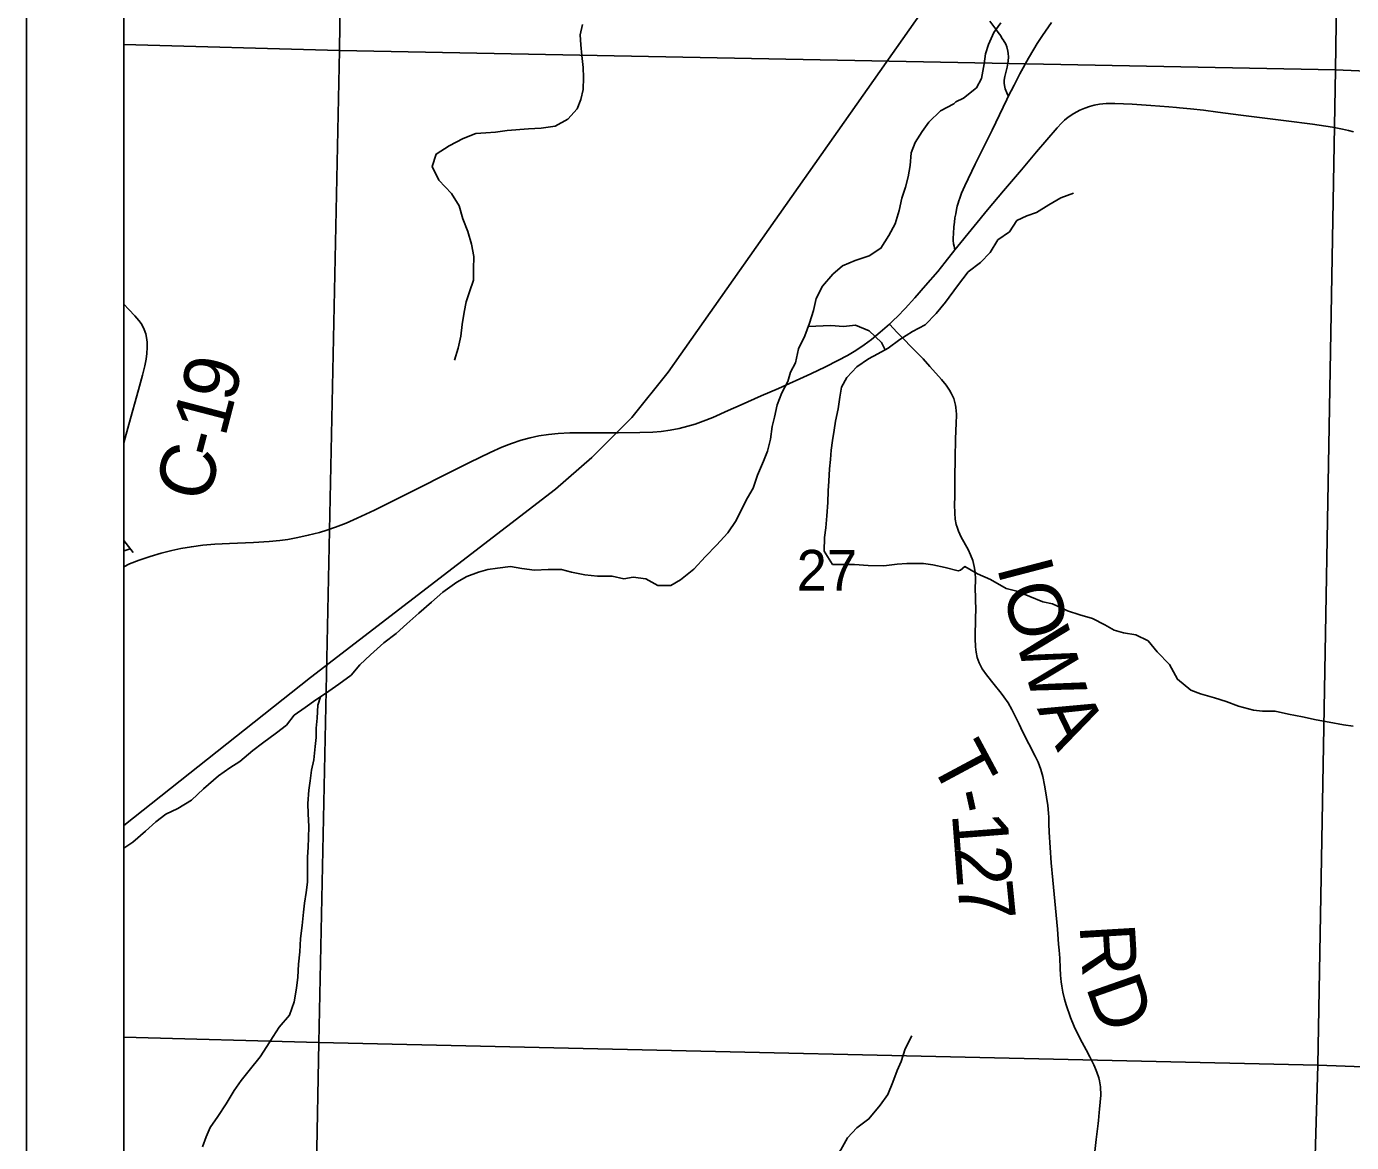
# Model space of a CAD drawing. Extents: x 0 to 34, y 0 to 22.
# Drawn here: x 2 to 3.363, y 16.577 to 17.725 of the extents above; entities that cross this region are included whole.
import ezdxf

# ---------------------------------------------------------------- set-up
doc = ezdxf.new("R2010")
doc.units = 0
for name, color, linetype in [('GM_X_Corporation', 7, 'Continuous'), ('GM_X_County_Road', 7, 'Continuous'), ('GM_X_County_Road_Text', 7, 'Continuous'), ('GM_X_Minor_River', 7, 'Continuous'), ('GM_X_Rail_Line', 7, 'Continuous'), ('GM_X_Section_Text', 7, 'Continuous'), ('GM_X_State_Route', 7, 'Continuous'), ('GM_X_Township_Road', 7, 'Continuous'), ('GM_X_Township_Road_Text', 7, 'Continuous'), ('SH_Data', 7, 'Continuous')]:
    doc.layers.add(name, color=color, linetype=linetype)

msp = doc.modelspace()

# ---------------------------------------------------------------- linework, layer by layer
at = {"layer": 'GM_X_Corporation'}
for points in [[(8.9, 20.9), (2.1, 20.9), (2.1, 15.6606)], [(5.3543, 16.3597), (5.3699, 17.5116), (5.3717, 17.6123), (4.6401, 17.6298), (4.3705, 17.6391), (4.3669, 17.8198), (4.37, 17.9048), (4.3768, 18.4091), (4.3782, 18.6502), (4.377, 18.6713), (3.7035, 18.69), (3.3642, 18.7005), (3.3691, 19.5041), (3.3724, 19.7263), (3.3869, 20.7918), (3.3886, 20.9), (2.1, 20.9), (2.1, 15.6606)], [(4.352, 16.8239), (4.3481, 16.6188), (3.3284, 16.656), (3.3465, 17.6805), (4.3675, 17.6365), (4.3565, 17.0622)]]:
    msp.add_lwpolyline(points, dxfattribs=at)
for points in [[(2.1, 18.7299), (2.1, 17.7065), (2.3219, 17.7003), (2.3352, 18.7231)], [(2.3352, 18.7231), (3.3614, 18.7006), (3.3465, 17.6805), (2.3219, 17.7003)], [(4.3772, 18.6714), (4.3675, 17.6365), (3.3465, 17.6805), (3.3614, 18.7006)], [(2.1, 17.7065), (2.1, 16.6849), (2.3008, 16.6793), (2.3219, 17.7003)], [(2.3219, 17.7003), (3.3465, 17.6805), (3.3284, 16.656), (2.3008, 16.6793)], [(2.1, 16.6849), (2.1, 15.6631), (2.2815, 15.6586), (2.3008, 16.6793)], [(2.3008, 16.6793), (3.3284, 16.656), (3.2981, 15.6275), (2.3289, 15.6573), (2.2815, 15.6586)]]:
    msp.add_lwpolyline(points, close=True, dxfattribs=at)
at = {"layer": 'GM_X_County_Road'}
msp.add_lwpolyline([(2.1, 17.2956), (2.1006, 17.2979), (2.1054, 17.3153), (2.1151, 17.3511), (2.1192, 17.366), (2.1216, 17.3756), (2.1231, 17.3828), (2.1238, 17.3883), (2.1242, 17.3945), (2.124, 17.4001), (2.1234, 17.405), (2.1226, 17.4086), (2.1209, 17.4133), (2.1196, 17.4161), (2.1178, 17.4194), (2.1156, 17.4224), (2.1116, 17.4271), (2.1052, 17.4339), (2.1, 17.4391)], dxfattribs=at)
at = {"layer": 'GM_X_Minor_River'}
for points in [[(2.5718, 17.7271), (2.5696, 17.7164), (2.5701, 17.7062), (2.5714, 17.6952), (2.5726, 17.6827), (2.5731, 17.6725), (2.5725, 17.66), (2.5703, 17.6497), (2.5663, 17.6402), (2.5569, 17.6295), (2.5437, 17.6225), (2.5294, 17.6205), (2.5165, 17.6196), (2.4946, 17.6178), (2.4825, 17.6162), (2.4726, 17.6157), (2.4621, 17.6148), (2.4492, 17.6098), (2.4349, 17.6021), (2.4214, 17.5936), (2.4174, 17.581), (2.4243, 17.5667), (2.4373, 17.5532), (2.445, 17.5404), (2.449, 17.5271), (2.454, 17.5139), (2.4576, 17.5011), (2.46, 17.4882), (2.4597, 17.4753), (2.4598, 17.464), (2.4558, 17.4518), (2.4521, 17.4415), (2.4503, 17.4309), (2.4482, 17.4183), (2.4468, 17.4062), (2.4439, 17.394), (2.4402, 17.3815)], [(2.956, 17.6473), (2.964, 17.6511), (2.9772, 17.6619), (2.9825, 17.6714), (2.985, 17.6866), (2.9864, 17.6968), (2.9894, 17.7063), (2.995, 17.7189), (3.0021, 17.7288)], [(2.956, 17.6473), (2.9538, 17.6454), (2.9402, 17.6381), (2.9282, 17.6266), (2.9215, 17.617), (2.9141, 17.6056), (2.91, 17.5949), (2.909, 17.582), (2.9069, 17.5702), (2.9043, 17.5596), (2.9003, 17.5482), (2.8978, 17.5356), (2.8934, 17.5219), (2.887, 17.5098), (2.8789, 17.4968), (2.8668, 17.4891), (2.8525, 17.484), (2.8393, 17.4785), (2.8295, 17.4701), (2.8187, 17.4579), (2.8124, 17.4449), (2.8095, 17.4327), (2.8055, 17.4198), (2.8007, 17.4065), (2.794, 17.3932), (2.7911, 17.3787), (2.7859, 17.3692), (2.783, 17.3597), (2.7771, 17.3479), (2.7723, 17.3357), (2.7694, 17.3228), (2.7672, 17.3133), (2.7654, 17.3004), (2.7622, 17.2878), (2.7581, 17.2775), (2.7518, 17.2631), (2.7474, 17.2498), (2.7418, 17.2399), (2.7348, 17.2265), (2.73, 17.2166), (2.7214, 17.204), (2.7098, 17.1914), (2.6986, 17.1795), (2.6866, 17.1665), (2.6727, 17.1557), (2.6629, 17.1496), (2.6493, 17.1498), (2.6371, 17.1565), (2.6242, 17.1583), (2.6144, 17.1566), (2.6023, 17.1592), (2.5875, 17.1594), (2.5742, 17.1608), (2.5606, 17.1633), (2.5503, 17.1662), (2.5367, 17.1661), (2.5227, 17.1655), (2.5094, 17.1673), (2.4977, 17.1694), (2.4845, 17.1674), (2.4746, 17.1662), (2.4648, 17.1634), (2.4528, 17.1591), (2.4426, 17.1533), (2.4283, 17.1429), (2.4167, 17.1326), (2.4036, 17.1214), (2.3912, 17.1103), (2.3803, 17.1004), (2.3675, 17.0907), (2.3537, 17.0785), (2.3428, 17.0681), (2.3338, 17.0574), (2.3214, 17.0482), (2.3075, 17.0386), (2.2977, 17.032), (2.2865, 17.0243), (2.2752, 17.0162), (2.2674, 17.0059), (2.2572, 16.9982), (2.2426, 16.9875), (2.2328, 16.9798), (2.2193, 16.9686), (2.2091, 16.9621), (2.1975, 16.954), (2.1821, 16.9406), (2.1697, 16.9287), (2.1555, 16.9202), (2.1434, 16.9144), (2.1329, 16.9067), (2.1224, 16.8971), (2.1093, 16.8856), (2.1, 16.8796)], [(2.9578, 17.4582), (2.9687, 17.4724), (2.9812, 17.482), (2.9913, 17.4923), (2.9992, 17.5053), (3.0113, 17.5138), (3.0188, 17.5252), (3.029, 17.5302), (3.0388, 17.5337), (3.0516, 17.5414), (3.0641, 17.5487), (3.0769, 17.5534)], [(2.9606, 17.1656), (2.9584, 17.1648), (2.9451, 17.1681), (2.9322, 17.171), (2.9227, 17.1724), (2.9057, 17.1722), (2.8955, 17.1717), (2.8818, 17.1701), (2.8659, 17.1703), (2.8519, 17.1713), (2.8421, 17.1712), (2.8292, 17.1714), (2.8204, 17.185), (2.821, 17.199), (2.8224, 17.2092), (2.8234, 17.2214), (2.8244, 17.235), (2.8247, 17.2472), (2.8253, 17.257), (2.8259, 17.2699), (2.827, 17.2794), (2.8276, 17.2889), (2.829, 17.2988), (2.8308, 17.3094), (2.8322, 17.3189), (2.8348, 17.3314), (2.8365, 17.3436), (2.8383, 17.3538), (2.8439, 17.3637), (2.854, 17.3748), (2.866, 17.3829), (2.8758, 17.388), (2.8863, 17.3941), (2.8984, 17.403), (2.9115, 17.4111), (2.9243, 17.418), (2.9359, 17.4295), (2.9453, 17.4414), (2.9578, 17.4582)], [(2.8834, 17.3924), (2.8795, 17.3997), (2.8669, 17.4117), (2.8528, 17.4177), (2.8403, 17.4164), (2.8274, 17.4174), (2.804, 17.4164)], [(2.1, 17.196), (2.1, 17.196), (2.1096, 17.1836)], [(2.1065, 17.1876), (2.1005, 17.1854), (2.1, 17.1854)], [(2.9606, 17.1656), (2.9652, 17.1692), (2.9781, 17.1617), (2.9915, 17.1558), (3.0078, 17.1468), (3.0188, 17.1438), (3.0321, 17.1383), (3.0454, 17.133), (3.0553, 17.1308), (3.0709, 17.1238), (3.0835, 17.1197), (3.0964, 17.1156), (3.1093, 17.1093), (3.1188, 17.1037), (3.1283, 17.1011), (3.1412, 17.0989), (3.1538, 17.0929), (3.163, 17.0816), (3.1756, 17.0684), (3.184, 17.0533), (3.1977, 17.0421), (3.2076, 17.0383), (3.2221, 17.0343), (3.2342, 17.0302), (3.2468, 17.0254), (3.262, 17.0213), (3.2714, 17.0203), (3.2843, 17.0204), (3.298, 17.0174), (3.3124, 17.0145), (3.3265, 17.0116), (3.3401, 17.009), (3.3549, 17.0065), (3.3648, 17.0051)], [(2.3024, 17.0352), (2.2997, 17.0267), (2.2991, 17.0131), (2.298, 17.0028), (2.2978, 16.9933), (2.2971, 16.9839), (2.2954, 16.9702), (2.2932, 16.9596), (2.2918, 16.9486), (2.2904, 16.9391), (2.2894, 16.9254), (2.2899, 16.9148), (2.2904, 16.9019), (2.2901, 16.8902), (2.2899, 16.8803), (2.2892, 16.8701), (2.2889, 16.8606), (2.2891, 16.8443), (2.2877, 16.8337), (2.2859, 16.823), (2.2849, 16.8135), (2.2835, 16.7999), (2.2817, 16.7866), (2.2811, 16.7729), (2.2797, 16.76), (2.2791, 16.7468), (2.2777, 16.7354), (2.2752, 16.7213), (2.2704, 16.7076), (2.26, 16.6954), (2.2536, 16.6858), (2.2473, 16.6755), (2.2402, 16.6648), (2.229, 16.6507), (2.2208, 16.6404), (2.2137, 16.6301), (2.2055, 16.6163), (2.1969, 16.6034), (2.1891, 16.5919), (2.1847, 16.5824), (2.181, 16.5721)], [(2.7713, 16.5074), (2.7853, 16.5148), (2.7973, 16.5221), (2.8082, 16.5298), (2.8202, 16.5401), (2.825, 16.5497), (2.8295, 16.5592), (2.8377, 16.5691), (2.8444, 16.5813), (2.8541, 16.5917), (2.8665, 16.6009), (2.8781, 16.6151), (2.8859, 16.6258), (2.8911, 16.6387), (2.8955, 16.6505), (2.8996, 16.66), (2.904, 16.6729), (2.9107, 16.6863)]]:
    msp.add_lwpolyline(points, dxfattribs=at)
at = {"layer": 'GM_X_Rail_Line'}
msp.add_lwpolyline([(3.6829, 18.8279), (3.1625, 18.0833), (2.66, 17.3693), (2.6227, 17.3226), (2.5817, 17.2815), (2.544, 17.2487), (2.292, 17.055), (2.1, 16.9029)], dxfattribs=at)
at = {"layer": 'GM_X_State_Route'}
msp.add_line((2.8876, 17.4186), (2.8918, 17.4227), dxfattribs=at)
for points in [[(3.0099, 17.6528), (3.0159, 17.6646), (3.0219, 17.6762), (3.0308, 17.6925), (3.0361, 17.7016), (3.0397, 17.7074), (3.0452, 17.7156), (3.0543, 17.7289)], [(2.955, 17.495), (2.9541, 17.499), (2.9537, 17.5013), (2.9533, 17.5046), (2.9533, 17.5071), (2.9535, 17.5121), (2.9539, 17.5188), (2.9545, 17.5237), (2.9551, 17.528), (2.9558, 17.5323), (2.9566, 17.5365), (2.9574, 17.5399), (2.9583, 17.5431), (2.9591, 17.5457), (2.96, 17.5483), (2.9619, 17.5535), (2.9651, 17.5609), (2.976, 17.5832), (2.9878, 17.6072), (2.9932, 17.6184), (3.0084, 17.6497), (3.0099, 17.6528)], [(2.955, 17.495), (2.9747, 17.5196), (2.9886, 17.5362), (3.0049, 17.5557), (3.0234, 17.5775), (3.0389, 17.5959), (3.0603, 17.6208), (3.0646, 17.6254), (3.0678, 17.6284), (3.0716, 17.6317), (3.0774, 17.6354), (3.0835, 17.6387), (3.0886, 17.641), (3.0934, 17.6427), (3.0982, 17.644), (3.1038, 17.645), (3.1106, 17.6456), (3.1194, 17.6457), (3.1373, 17.645), (3.1565, 17.6438), (3.175, 17.6423), (3.183, 17.6416), (3.1861, 17.6413), (3.1972, 17.6403), (3.2108, 17.6388), (3.2256, 17.6369), (3.249, 17.6337), (3.2737, 17.6306), (3.2959, 17.6278), (3.323, 17.6244), (3.3433, 17.6212), (3.3537, 17.6193), (3.3598, 17.618), (3.3652, 17.6166)], [(2.8918, 17.4227), (2.896, 17.4267), (2.9038, 17.4348), (2.9137, 17.4458), (2.9248, 17.4584), (2.9373, 17.4729), (2.9451, 17.4825), (2.955, 17.495)], [(2.3446, 17.221), (2.3581, 17.2272), (2.3787, 17.2374), (2.4558, 17.2762), (2.4771, 17.2866), (2.489, 17.292), (2.4988, 17.2959), (2.5089, 17.2993), (2.518, 17.3017), (2.5271, 17.3036), (2.537, 17.3051), (2.5469, 17.3061), (2.5588, 17.3067), (2.5768, 17.3068), (2.6085, 17.3068), (2.6308, 17.307), (2.6444, 17.3075), (2.653, 17.3083), (2.6622, 17.3096), (2.6713, 17.3114), (2.6803, 17.3136), (2.688, 17.3159), (2.6961, 17.3188), (2.7059, 17.3227), (2.7217, 17.3297), (2.7353, 17.3357), (2.7558, 17.3448), (2.7734, 17.3526), (2.8069, 17.3675), (2.822, 17.3747), (2.8347, 17.3812), (2.8445, 17.3865), (2.853, 17.3916), (2.8617, 17.3975), (2.8691, 17.403), (2.8783, 17.4104), (2.8876, 17.4186)], [(2.1, 17.1691), (2.1061, 17.1719), (2.1159, 17.1758), (2.1272, 17.1796), (2.1385, 17.183), (2.1494, 17.1857), (2.1586, 17.1877), (2.1696, 17.1896), (2.1814, 17.1911), (2.1938, 17.1921), (2.2087, 17.1929), (2.2335, 17.194), (2.2496, 17.195), (2.2607, 17.1961), (2.2687, 17.1972), (2.279, 17.199), (2.2899, 17.2014), (2.3013, 17.2044), (2.309, 17.2067), (2.3177, 17.2097), (2.3287, 17.214), (2.3401, 17.2189), (2.3446, 17.221)]]:
    msp.add_lwpolyline(points, dxfattribs=at)
at = {"layer": 'GM_X_Township_Road'}
msp.add_line((2.8876, 17.4186), (2.8918, 17.4227), dxfattribs=at)
for points in [[(3.0099, 17.6528), (3.0093, 17.6544), (3.0083, 17.6567), (3.0068, 17.6609), (3.006, 17.6643), (3.0057, 17.6667), (3.0058, 17.6698), (3.0065, 17.6734), (3.0074, 17.6777), (3.0087, 17.6831), (3.0098, 17.6892), (3.0101, 17.6936), (3.0099, 17.6973), (3.0095, 17.6997), (3.0084, 17.7039), (3.0073, 17.7068), (3.0048, 17.7111), (3.0034, 17.7131), (3.0021, 17.7152), (2.9996, 17.7188), (2.997, 17.7223), (2.9911, 17.7303)], [(2.955, 17.495), (2.9541, 17.499), (2.9537, 17.5013), (2.9533, 17.5046), (2.9533, 17.5071), (2.9535, 17.5121), (2.9539, 17.5188), (2.9545, 17.5237), (2.9551, 17.528), (2.9558, 17.5323), (2.9566, 17.5365), (2.9574, 17.5399), (2.9583, 17.5431), (2.9591, 17.5457), (2.96, 17.5483), (2.9619, 17.5535), (2.9651, 17.5609), (2.976, 17.5832), (2.9878, 17.6072), (2.9932, 17.6184), (3.0084, 17.6497), (3.0099, 17.6528)], [(2.8918, 17.4227), (2.896, 17.4267), (2.9038, 17.4348), (2.9137, 17.4458), (2.9248, 17.4584), (2.9373, 17.4729), (2.9451, 17.4825), (2.955, 17.495)], [(3.0986, 16.5642), (3.1004, 16.5796), (3.1016, 16.5907), (3.1023, 16.5962), (3.1026, 16.5993), (3.1035, 16.6073), (3.1039, 16.611), (3.105, 16.6253), (3.1048, 16.6339), (3.1037, 16.64), (3.103, 16.643), (3.101, 16.6489), (3.0989, 16.6541), (3.0978, 16.6564), (3.0937, 16.6647), (3.0899, 16.6718), (3.0858, 16.6794), (3.0824, 16.686), (3.0776, 16.6961), (3.0739, 16.7053), (3.0693, 16.7181), (3.0677, 16.7241), (3.066, 16.7314), (3.0651, 16.7375), (3.0644, 16.7418), (3.0638, 16.7486), (3.0634, 16.756), (3.0629, 16.7664), (3.0622, 16.7744), (3.0617, 16.7806), (3.0606, 16.7961), (3.0557, 16.8464), (3.0539, 16.8645), (3.0521, 16.896), (3.0517, 16.9044), (3.0518, 16.9081), (3.0516, 16.9112), (3.0514, 16.9155), (3.0506, 16.9234), (3.0493, 16.9319), (3.0489, 16.9344), (3.0473, 16.9442), (3.0454, 16.9533), (3.0434, 16.9604), (3.0406, 16.9679), (3.0377, 16.974), (3.0312, 16.9867), (3.0281, 16.9928), (3.0229, 17.0033), (3.021, 17.0072), (3.0178, 17.0138), (3.0137, 17.0221), (3.0097, 17.029), (3.0055, 17.0351), (3.0025, 17.039), (2.9955, 17.0477), (2.9874, 17.0579), (2.9831, 17.0639), (2.9799, 17.07), (2.978, 17.0757), (2.9769, 17.0812), (2.9763, 17.0867), (2.976, 17.0953), (2.9759, 17.0997), (2.976, 17.1046), (2.9761, 17.1083), (2.9762, 17.1126), (2.9763, 17.1164), (2.9763, 17.1194), (2.9764, 17.1219), (2.9764, 17.1256), (2.9764, 17.1281), (2.9763, 17.1318), (2.9762, 17.136), (2.9762, 17.1379), (2.976, 17.1459), (2.9761, 17.1558), (2.9758, 17.1633), (2.9749, 17.1694), (2.9734, 17.1754), (2.9712, 17.1812), (2.9685, 17.1868), (2.9615, 17.1993), (2.9586, 17.2055), (2.9572, 17.2096), (2.9564, 17.2126), (2.9554, 17.2181), (2.9549, 17.2243), (2.9547, 17.233), (2.9549, 17.241), (2.9551, 17.2591), (2.9552, 17.282), (2.9556, 17.2994), (2.956, 17.31), (2.9563, 17.3156), (2.9565, 17.3262), (2.956, 17.333), (2.9556, 17.3354), (2.9539, 17.342), (2.9513, 17.3476), (2.9495, 17.3508), (2.9459, 17.3559), (2.9412, 17.3617), (2.9292, 17.3752), (2.9223, 17.3831), (2.9169, 17.3883), (2.8956, 17.4102), (2.8876, 17.4186)]]:
    msp.add_lwpolyline(points, dxfattribs=at)
at = {"layer": 'SH_Data'}
for p, q in [((2, 21), (2, 14)), ((2.1, 20.9), (2.1, 14.1))]:
    msp.add_line(p, q, dxfattribs=at)

# ---------------------------------------------------------------- texts
at = {"layer": 'GM_X_County_Road_Text'}
for s, rotation, p in [('9', 77.1274, (2.2135, 17.3369)), ('1', 75.4052, (2.2043, 17.3013)), ('-', 75.24, (2.1983, 17.2785)), ('C', 75.1998, (2.1863, 17.2334))]:
    msp.add_text(s, height=0.0568, rotation=rotation, dxfattribs=at).set_placement(p)
at = {"layer": 'GM_X_Section_Text'}
msp.add_text('27', height=0.04186, rotation=0, dxfattribs=at).set_placement((2.7922, 17.1445))
at = {"layer": 'GM_X_Township_Road_Text'}
for s, rotation, p in [('I', 284.6554, (2.9979, 17.169)), ('O', 283.9735, (3.0038, 17.1466)), ('W', 286.6871, (3.0166, 17.0952)), ('A', 295.745, (3.0391, 17.023)), ('T', 298.2154, (2.9285, 16.9693)), ('-', 282.5187, (2.9472, 16.9357)), ('1', 274.4278, (2.9519, 16.915)), ('2', 274.2451, (2.9546, 16.8802)), ('7', 275.6433, (2.9573, 16.8438)), ('R', 273.4367, (3.0832, 16.8003)), ('D', 289.3425, (3.0893, 16.7371))]:
    msp.add_text(s, height=0.0568, rotation=rotation, dxfattribs=at).set_placement(p)

doc.saveas('drawing.dxf')
